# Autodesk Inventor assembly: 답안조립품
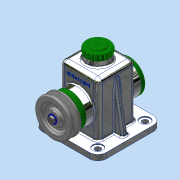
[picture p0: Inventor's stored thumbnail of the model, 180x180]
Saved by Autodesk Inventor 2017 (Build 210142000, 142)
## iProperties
Part Number: 답안조립품
Material: 일반
Document SubType Name: Assembly
Designer: MRC
Author: MRC
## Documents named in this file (14)
- C:\Users\MRC\Desktop\700907V1007\답안조립품.iam
- C:\Users\MRC\Desktop\700907V1007\본체.ipt
- C:\Users\MRC\Desktop\700907V1007\V-벨트풀리.ipt
- C:\Users\MRC\Desktop\700907V1007\뒤커버.ipt
- C:\Users\MRC\Desktop\700907V1007\멈춤링 15 x 1.ipt
- C:\Users\MRC\Desktop\700907V1007\베어링 15 x 35 x 11.ipt
- C:\Users\MRC\Desktop\700907V1007\볼트 M4 x 10.ipt
- C:\Users\MRC\Desktop\700907V1007\볼트 M6 x 12.ipt
- C:\Users\MRC\Desktop\700907V1007\상부캡.ipt
- C:\Users\MRC\Desktop\700907V1007\앞커버.ipt
- C:\Users\MRC\Desktop\700907V1007\오일실 15 25 7.ipt
- C:\Users\MRC\Desktop\700907V1007\와셔.ipt
- C:\Users\MRC\Desktop\700907V1007\축.ipt
- C:\Users\MRC\Desktop\700907V1007\키 5 x 5 x 14.ipt
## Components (1 placed, 1 different names)
1. V-벨트풀리:1
